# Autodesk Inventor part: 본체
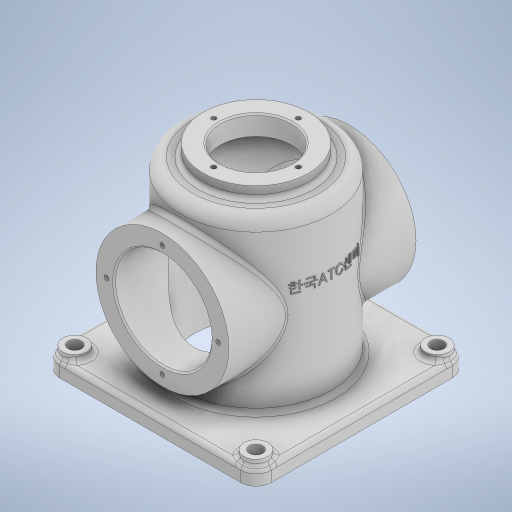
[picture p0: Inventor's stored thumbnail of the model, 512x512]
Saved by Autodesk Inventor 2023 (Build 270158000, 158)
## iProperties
Created: 2025-05
Part Number: 본체
Material: 일반
Document SubType Name: Modeling
Designer: Admin
Density: 1 g/cm^3
Appearance: 기본값
Author: Admin
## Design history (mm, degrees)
sketch "스케치1"
  geometry: L1 (-70, 70)-(70, 70); L2 (70, 70)-(70, -70); L3 (70, -70)-(-70, -70); L4 (-70, -70)-(-70, 70); L5 (-70, 70)-(70, -70); L6 (70, 70)-(-70, -70); 1 further point
  constraints: 12 end point, 2 midpoint, 2 parallel, 1 horizontal, 1 perpendicular
  dimensions: "d0" = 140 distance of L1.end L2.end; "d1" = 140 distance of L2.end L3.end
extrude "돌출1" new body sketch "스케치1" distance "d2" = 10; taper "d3" = 0 deg
sketch "스케치2"
  geometry: C1 r 50 at (0, 0); 1 further point
  constraints: 1 centre point, 1 coincident
  dimensions: "d4" = 100 diameter of C1
extrude "돌출2" join sketch "스케치2" distance "d5" = 112; taper "d6" = 0 deg
sketch "스케치3"
  geometry: C1 r 35 at (0, 0); 1 further point
  constraints: 1 centre point, 1 coincident
  dimensions: "d7" = 70 diameter of C1
extrude "돌출3" join sketch "스케치3" distance "d8" = 8; taper "d9" = 0 deg
sketch "스케치4"
  geometry: L1 (60, -60)-(-60, -60); L2 (-60, -60)-(-60, 60); L3 (-60, 60)-(60, 60); L4 (60, 60)-(60, -60); L5 (60, -60)-(-60, 60); L6 (-60, -60)-(60, 60); C1 r 8 at (-60, -60); C2 r 8 at (-60, 60); C3 r 8 at (60, -60); C4 r 8 at (60, 60); 1 further point
  constraints: 12 end point, 4 centre point, 4 coincident, 2 midpoint, 2 parallel, 1 horizontal, 1 perpendicular
  dimensions: "d10" = 120 distance of L1.end L2.end; "d11" = 120 distance of L2.end L3.end; "d12" = 16 diameter of C1; "d13" = 16 diameter of C2; "d14" = 16 diameter of C4; "d15" = 16 diameter of C3
extrude "돌출4" join sketch "스케치4" distance "d16" = 4; taper "d17" = 0 deg
sketch "스케치5"
  geometry: L1 (70, 0)-(-70, 0) reference; L2 (0, -26)-(0, 156) reference; C1 r 44 at (0, 65); 1 further point
  constraints: 1 centre point, 1 midpoint
  dimensions: "d18" = 88 diameter of C1; "d19" = 65 distance from line of L1 C1.centre
extrude "돌출5" join sketch "스케치5" stored distance "d20" = 124; taper "d21" = 0 deg
sketch "스케치8" dims "d23" = 74
  geometry: L1 (0, -91)-(0, 91) reference; L2 (-98, -65)-(98, -65) reference; 7 further points
  constraints: 1 coincident, 1 midpoint, 1 point on line, 1 vertical alignment, 7 other
  dimensions: "d24" = 65 distance from line of L2 point (0, 0); "d27" = 360 deg dimension on point (0, 0) point (0, 37) (derived)
hole "구멍1" sketch "스케치8" at (0, 37), (-37, 0), (0, -37), (37, 0) diameter "d29" = 3.242; stored, may be unused: countersink angle "d33" = 90 deg, drill point angle "d35" = 118 deg; dims "d30" = 8, "d31" = 4, "d32" = 2, "d34" = 10
sketch "스케치10"
  geometry: L1 (-98, -65)-(98, -65) reference; L2 (0, -91)-(0, 91) reference; C1 r 32 at (0, 0); 1 further point
  constraints: 1 centre point, 1 midpoint
  dimensions: "d36" = 64 diameter of C1; "d37" = 65 distance from line of L1 C1.centre
extrude "돌출6" cut sketch "스케치10" distance "d38" = 124; taper "d39" = 0 deg
sketch "스케치11" dims "d40" = 56
  geometry: L1 (-98, 0)-(98, 0) reference; 6 further points
  constraints: 1 coincident, 1 horizontal alignment, 1 point on line, 7 other
  dimensions: "d43" = 360 deg dimension on point (0, 0) point (-28, 0) (derived)
hole "구멍2" sketch "스케치11" at (-28, 0), (0, -28), (28, 0), (0, 28) diameter "d45" = 3.242; stored, may be unused: countersink angle "d49" = 90 deg, drill point angle "d51" = 118 deg; dims "d46" = 8, "d47" = 4, "d48" = 2, "d50" = 10
sketch "스케치12"
  geometry: C1 r 23.5 at (0, 0); 1 further point
  constraints: 1 centre point, 1 coincident
  dimensions: "d52" = 47 diameter of C1
extrude "돌출7" cut sketch "스케치12" distance "d53" = 13; taper "d54" = 0 deg
sketch "스케치13"
  geometry: L1 (-158, -60)-(38, -60) reference; L2 (-60, 38)-(-60, -158) reference; C1 r 4.5 at (0, 0); C2 r 8 at (0, 0) reference; C3 r 4.5 at (-120, 0); C4 r 4.5 at (-120, -120); C5 r 4.5 at (0, -120); 1 further point
  constraints: 4 centre point, 3 symmetric about line, 1 concentric, 3 other
  dimensions: "d55" = 9 diameter of C1
extrude "돌출8" cut sketch "스케치13" extent not by distance; stored distance "d56" = 0; taper "d57" = 0 deg
sketch "스케치14"
  geometry: C1 r 41 at (0, 0); 1 further point
  constraints: 1 centre point, 1 coincident
  dimensions: "d58" = 82 diameter of C1
extrude "돌출9" cut sketch "스케치14" distance "d59" = 117; taper "d60" = 0 deg
node "작업 평면1"
sketch "스케치15"
  geometry: L1 (0, 70)-(0, -70) reference; L2 (-130.999, 0)-(173.5, 0) reference; 2 further points
  constraints: 1 point on line, 1 other
  dimensions: "d65" = 80 distance from line of L1 point (80, 0)
feature "엠보싱2" sketch "스케치15" dims "d0" = 140, "d1" = 140, "d10" = 120, "d11" = 120, "d12" = 16, "d13" = 16, "d14" = 16, "d15" = 16, "d66" = 0.5, "d67" = 0
fillet "모깎기1" dims "d68" = 10
fillet "모깎기2" dims "d69" = 3
fillet "모깎기3" dims "d70" = 3
fillet "모깎기4" dims "d71" = 8
chamfer "모따기1" distance "d72" = 1; stored, may be unused: second distance "d73" = 2, angle "d74" = 45 deg
fillet "모깎기5" dims "d75" = 3
node "솔리드1"
mirror "미러1"
feature "A9D066F2-1C7D-4E18-AEED-F7BC21143FA4" dims "d29" = 3.242, "d30" = 8, "d31" = 4, "d32" = 2, "d33" = 90 deg, "d34" = 10, "d35" = 118 deg
other parameters: "d61" = 89
